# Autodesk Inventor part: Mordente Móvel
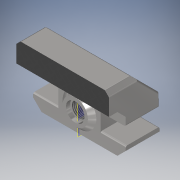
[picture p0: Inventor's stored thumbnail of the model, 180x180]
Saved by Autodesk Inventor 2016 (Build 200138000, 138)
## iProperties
Created: 2016-02
Part Number: Mordente Móvel
Material: Steel, Carbon
Document SubType Name: Modeling
Designer: Vertex
Mass: 2400.66 g
Surface Area: 389.201 cm^2
Volume: 305.817 cm^3
Density: 7.85 g/cm^3
Appearance: Semi-Polished
Title: Apoio
Author: Vertex
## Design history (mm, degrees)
sketch "Sketch1"
  geometry: L1 (85.224, 80)-(35.224, 80); L2 (30.224, 15)-(30.224, 0); L3 (30.224, 15)-(60.224, 15); L4 (60.224, 35)-(60.224, 15); L5 (30.224, 35)-(60.224, 35); L6 (30.224, 75)-(30.224, 35); L7 (30.224, 75)-(35.224, 80); L8 (85.224, 80)-(135.224, 80); L9 (140.224, 15)-(140.224, 0); L10 (140.224, 15)-(110.224, 15); L11 (110.224, 35)-(110.224, 15); L12 (140.224, 35)-(110.224, 35); L13 (140.224, 75)-(140.224, 35); L14 (140.224, 75)-(135.224, 80); L15 (30.224, 0)-(140.224, 0); L16 (85.224, 90.232)-(85.224, -5); 5 further points
  constraints: 32 end point, 5 point on line, 2 parallel, 1 horizontal, 1 vertical
  dimensions: "d5" = 5 distance of L6.start point (30.224, 80); "d6" = 5 distance of L1.end point (30.224, 80) (= d5); "d9" = 20 distance between parallel lines of L12 L10; "d10" = 45 distance from line of L8 L12.start; "d67" = 15 distance of L9.end L9.start; "d68" = 45 vertical distance of L5.start L1.end; "d89" = 30 distance of L4.start L5.start; "d90" = 30 distance between parallel lines of L13 L11; "d94" = 110 distance of L9.end L2.end; "d95" = 30 distance of L2.start L3.end; "d96" = 110 distance between parallel lines of L13 L6
extrude "Extrusion1" new body sketch "Sketch1" stored distance "d11" = 40; taper "d12" = 0 deg
hole "Hole1" diameter "d15" = 17.83; stored, may be unused: countersink angle "d19" = 90 deg, drill point angle "d21" = 118 deg; dims "d13" = 25, "d14" = 25, "d16" = 40, "d17" = 3.75, "d18" = 2.5, "d20" = 49.3
workplane "Work Plane1"
sketch "Sketch2"
  geometry: C1 r 8.915 at (85.224, 25) reference; C2 r 11 at (85.224, 25); C3 r 20 at (85.224, 25); 1 further point
  constraints: 2 centre point, 2 coincident
  dimensions: "d92" = 22 diameter of C2; "d93" = 40 diameter of C3
extrude "Extrusion2" join sketch "Sketch2" distance "d35" = 5; taper "d36" = 0 deg
chamfer "Chamfer4" distance "d69" = 30; stored, may be unused: second distance "d70" = 1.25, angle "d71" = 45 deg
fillet "Fillet10" dims "d72" = 2
sketch "Sketch3"
  geometry: L1 (32.224, 35)-(60.224, 35) reference; L2 (60.224, 35)-(60.224, 13) reference; L3 (30.224, 13)-(60.224, 13) reference; L4 (30.224, 0)-(140.224, 0) reference; L5 (110.224, 13)-(140.224, 13) reference; L6 (110.224, 35)-(110.224, 13) reference; L7 (110.224, 35)-(138.224, 35) reference; L8 (140.224, 37)-(140.224, 74.172) reference; L9 (139.638, 75.586)-(135.809, 79.414) reference; L10 (134.395, 80)-(36.052, 80) reference; L11 (34.638, 79.414)-(30.809, 75.586) reference; L12 (30.224, 74.172)-(30.224, 37) reference; L13 (30.224, 74.172)-(30.224, 37) reference; L14 (30.224, 55)-(140.224, 55); L15 (140.224, 37)-(140.224, 74.172) reference; L16 (140.224, 0)-(140.224, 13) reference; L17 (30.224, 13)-(30.224, 0) reference; C1 r 8.915 at (85.224, 25) reference; C2 r 11 at (85.224, 25) reference; C3 r 20 at (85.224, 25) reference; A1 r 2 centre (32.224, 37) between (30.224, 37) and (32.224, 35) reference; A2 r 2 centre (138.224, 37) between (138.224, 35) and (140.224, 37) reference; A3 r 2 centre (138.224, 74.172) between (140.224, 74.172) and (139.638, 75.586) reference; A4 r 2 centre (134.395, 78) between (135.809, 79.414) and (134.395, 80) reference; A5 r 2 centre (36.052, 78) between (36.052, 80) and (34.638, 79.414) reference; A6 r 2 centre (32.224, 74.172) between (30.809, 75.586) and (30.224, 74.172) reference; 1 further point
  constraints: 2 end point, 2 point on line, 1 perpendicular
extrude "Extrusion3" join sketch "Sketch3" distance "d73" = 20; taper "d74" = 0 deg
chamfer "Chamfer5" distance "d75" = 10; stored, may be unused: second distance "d76" = 1.25, angle "d77" = 45 deg
mirror "Mirror8"
chamfer "Chamfer6" distance "d97" = 5; stored, may be unused: second distance "d98" = 1.25, angle "d99" = 45 deg
body "Solid1"
node "Projected Loop1"
